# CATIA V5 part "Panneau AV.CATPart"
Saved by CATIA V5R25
Part number: Panneau AV
Bounding box of the stored display mesh (mm): x -160 to 160, y -20 to 20, z 0 to 3
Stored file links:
  C:\Users\m000605\Desktop\Projet FAB liseuse\Panneau AV.CATPart
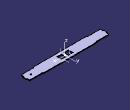
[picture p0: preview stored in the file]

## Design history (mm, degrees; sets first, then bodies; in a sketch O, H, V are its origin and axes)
AxisSystem1: origin (0, 0, 0), X (1, 0, 0), Y (0, 1, 0), Z (0, 0, 1)
Set1
  Sketch1 on XY plane of AxisSystem1, origin (0, 0, 0), H (1, 0, 0), V (0, 1, 0)
    line L1 (-160, 7) -> (-160, -7)
    line L2 (-160, -7) -> (-157, -7)
    line L3 (-107, -17) -> (-107, -20)
    line L4 (-107, -20) -> (107, -20)
    line L5 (107, -20) -> (107, -17)
    point P8 (157, -7)
    line L6 (157, -7) -> (160, -7)
    line L7 (160, -7) -> (160, 7)
    line L8 (160, 7) -> (157, 7)
    point P12 (107, 17)
    line L9 (107, 17) -> (107, 20)
    line L10 (-107, 20) -> (107, 20)
    line L11 (-107, 20) -> (-107, 17)
    line L12 (-157, 7) -> (-160, 7)
    reference intersected line E1 through (0, 0) direction (-1, 0) from ZX plane of AxisSystem1
    reference projected line E2 through (0, 0) direction (1, 0) from edge [XY plane of AxisSystem1 | ZX plane of AxisSystem1]
    line L13 (-107, -17) -> (-157, -17)
    line L14 (-157, -17) -> (-157, -7)
    line L15 (-157, 7) -> (-157, 17)
    line L16 (-157, 17) -> (-107, 17)
    line L17 (107, 17) -> (157, 17)
    line L18 (157, 17) -> (157, 7)
    line L19 (107, -17) -> (157, -17)
    point P20 (157, -17)
    line L20 (157, -17) -> (157, -7)
    reference intersected line E3 through (0, 0) direction (-1, 0) from ZX plane of AxisSystem1
    distance L4 L10 = 40
    distance L10 L17 = 3
    distance L13 L4 = 3
    distance L19 L6 = 10
    distance L7 L1 = 320
    distance L18 L9 = 50
    distance L20 L7 = 3
    distance L15 L11 = 50
    distance L1 L15 = 3
    distance L12 L16 = 10
    distance L14 L3 = 50
    vertical: L1 V, L3 V, L5 V, L7 V, L9 V, L11 V, L14 V, L15 V, L18 V, L20 V
    horizontal: L2 H, L4 H, L6 H, L8 H, L10 H, L12 H, L13 H, L16 H, L17 H, L19 H
    coincidence: P8 L2, P12 L5, P20 L18
    symmetry: L1 L7 V, L4 L10 E1, L8 L6 E2, L20 L14 V, L19 L17 H, L13 L16 E3
Body1 (main body)
  Pad1: profile Sketch1, direction (0, 0, 1), length 3
  Sketch2 on end face of Pad1, origin (0, 0, 3), H (1, 0, 0), V (0, 1, 0)
    line L1 (-23, 9) -> (-5, 9)
    line L2 (-5, 9) -> (-5, -9)
    line L3 (-5, -9) -> (-23, -9)
    line L4 (-23, -9) -> (-23, 9)
    point P5 (5, 9)
    line L5 (5, 9) -> (23, 9)
    line L6 (23, 9) -> (23, -9)
    line L7 (23, -9) -> (5, -9)
    line L8 (5, -9) -> (5, 9)
    point P7 (23, -9)
    length L5 = 18
    length L6 = 18
    length L1 = 18
    distance L2 V = 5
    horizontal: L1 H, L3 H, L5 H, L7 H
    vertical: L2 V, L4 V, L6 V, L8 V
    coincidence: P5 L1, P7 L3
    symmetry: L2 L8 V, L5 L7 H
  Pocket1: profile Sketch2, direction (0, 0, -1), length 3
  Sketch3 on end face of Pad1, origin (0, 0, 3), H (1, 0, 0), V (0, 1, 0)
    circle A1 centre (135, 0) radius 2.75
    point P1 (135, 0)
    reference projected line E1 (160, -7) -> (160, 7) from edge [face of Pad1 from Sketch1.L7 | end face of Pad1]
    radius A1 = 2.75
    distance P1 E1 = 25
    coincidence: P1 H
  Pocket2: profile Sketch3, direction (0, 0, -1), length 3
